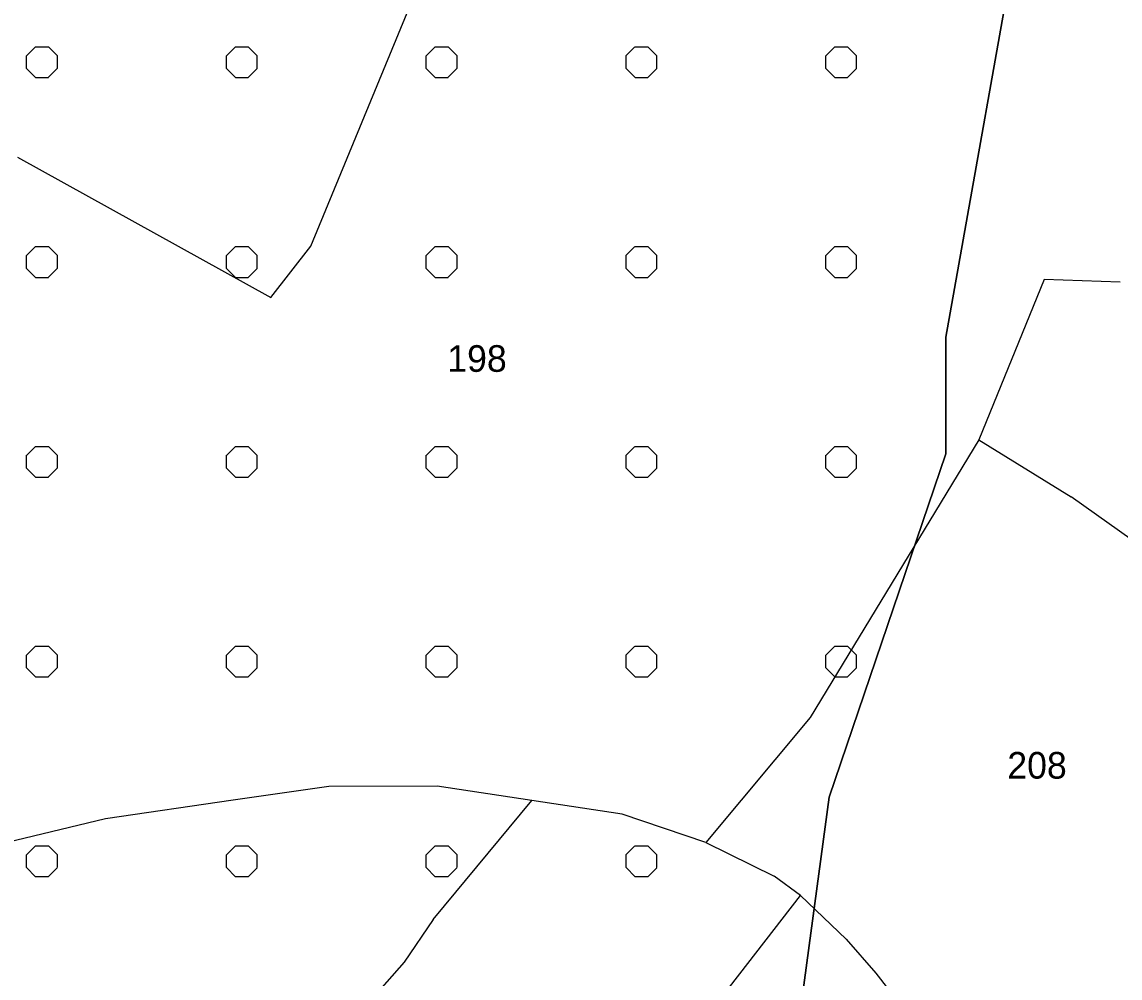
# Model space of a CAD drawing. Extents: x 410727 to 412947, y 4463506 to 4466382.
# Drawn here: x 411531.6 to 411696.5, y 4466009.6 to 4466153.2 of the extents above; entities that cross this region are included whole.
import ezdxf

# ---------------------------------------------------------------- set-up
doc = ezdxf.new("R2010")
doc.units = 0
for name, color, linetype in [('ADAKENARI', 7, 'Continuous'), ('KDS_PARSEL_NO', 7, 'Continuous'), ('KDS_PL', 7, 'Continuous'), ('PL_KA_TARIM_DIGER', 7, 'Continuous'), ('PL_KA_TARIM_OZEL', 7, 'Continuous'), ('TR_OZELMAHSUL', 7, 'Continuous')]:
    doc.layers.add(name, color=color, linetype=linetype)

msp = doc.modelspace()

# ---------------------------------------------------------------- linework, layer by layer
at = {"layer": 'ADAKENARI'}
for p, q in [((411670.3, 4466105.81), (411682.27, 4466173.05)), ((411670.3, 4466088.31), (411670.3, 4466105.81)), ((411652.8, 4466036.74), (411670.3, 4466088.31)), ((411646.35, 4465988.84), (411652.8, 4466036.74))]:
    msp.add_line(p, q, dxfattribs=at)
at = {"layer": 'KDS_PL'}
for p, q in [((411574.94, 4466119.47), (411590.62, 4466157.38)), ((411530.91, 4466132.84), (411568.94, 4466111.75)), ((411568.94, 4466111.75), (411574.94, 4466119.47)), ((411685.06, 4466114.5), (411675.28, 4466090.38)), ((411696.47, 4466114.09), (411685.06, 4466114.5)), ((411675.28, 4466090.38), (411649.91, 4466048.72)), ((411675.28, 4466090.38), (411689.12, 4466081.85)), ((411702.88, 4466072.06), (411689.12, 4466081.85)), ((411649.91, 4466048.72), (411634.28, 4466029.91)), ((411577.69, 4466038.34), (411563.31, 4466036.31)), ((411593.91, 4466038.38), (411577.69, 4466038.34)), ((411608.12, 4466036.25), (411593.91, 4466038.38)), ((411563.31, 4466036.31), (411544.12, 4466033.5)), ((411593.33, 4466018.34), (411608.12, 4466036.25)), ((411621.72, 4466034.16), (411608.12, 4466036.25)), ((411544.12, 4466033.5), (411521.38, 4466028)), ((411634.28, 4466029.91), (411621.72, 4466034.16)), ((411634.28, 4466029.91), (411644.52, 4466024.88)), ((411648.5, 4466021.99), (411644.52, 4466024.88)), ((411637.84, 4466008.22), (411648.5, 4466021.99)), ((411648.5, 4466021.99), (411655.33, 4466015.42)), ((411593.33, 4466018.34), (411588.96, 4466011.95)), ((411655.33, 4466015.42), (411659.81, 4466010.33)), ((411588.96, 4466011.95), (411584.53, 4466006.9)), ((411659.81, 4466010.33), (411664.6, 4466004.13))]:
    msp.add_line(p, q, dxfattribs=at)
at = {"layer": 'PL_KA_TARIM_DIGER'}
msp.add_lwpolyline([(411682.27, 4466173.05), (411670.3, 4466105.81), (411670.3, 4466088.31), (411652.8, 4466036.74), (411646.35, 4465988.84), (411635.3, 4465976.87), (411591.09, 4465931.74), (411538.25, 4465904.8), (411605.17, 4465869.8), (411613.8, 4465883.79), (411618.69, 4465897.02), (411620.41, 4465890.7), (411625.58, 4465882.65), (411631.77, 4465875.64), (411639.11, 4465868.28), (411648.52, 4465860.01), (411661.14, 4465849.78), (411670.66, 4465841.96), (411677.43, 4465836.56), (411684.65, 4465834.26), (411690.51, 4465834.49), (411698.65, 4465836.9)], dxfattribs=at)
at = {"layer": 'PL_KA_TARIM_OZEL'}
msp.add_lwpolyline([(411524.33, 4465912.08), (411524.97, 4465911.75), (411538.25, 4465904.8), (411538.25, 4465904.8), (411591.09, 4465931.74), (411635.3, 4465976.87), (411646.35, 4465988.84), (411652.8, 4466036.74), (411670.3, 4466088.31), (411670.3, 4466105.81), (411682.27, 4466173.05), (411679.51, 4466190.55), (411686.88, 4466263.31), (411695.17, 4466296.47), (411693.82, 4466320.72), (411344.35, 4466324.82)], dxfattribs=at)
at = {"layer": 'TR_OZELMAHSUL'}
for p, q in [((411532.28, 4466148.06), (411533.63, 4466149.41)), ((411533.64, 4466149.42), (411535.56, 4466149.42)), ((411536.91, 4466148.06), (411535.56, 4466149.41)), ((411562.28, 4466148.06), (411563.63, 4466149.41)), ((411563.64, 4466149.42), (411565.56, 4466149.42)), ((411566.91, 4466148.06), (411565.56, 4466149.41)), ((411592.27, 4466148.06), (411593.63, 4466149.41)), ((411593.64, 4466149.42), (411595.56, 4466149.42)), ((411596.91, 4466148.06), (411595.56, 4466149.41)), ((411622.27, 4466148.06), (411623.63, 4466149.41)), ((411623.64, 4466149.42), (411625.56, 4466149.42)), ((411626.91, 4466148.06), (411625.56, 4466149.41)), ((411652.27, 4466148.06), (411653.63, 4466149.41)), ((411653.64, 4466149.42), (411655.56, 4466149.42)), ((411656.91, 4466148.06), (411655.56, 4466149.41)), ((411532.29, 4466146.15), (411532.29, 4466148.07)), ((411536.91, 4466146.15), (411536.91, 4466148.07)), ((411562.29, 4466146.15), (411562.29, 4466148.07)), ((411566.91, 4466146.15), (411566.91, 4466148.07)), ((411592.29, 4466146.15), (411592.29, 4466148.07)), ((411596.91, 4466146.15), (411596.91, 4466148.07)), ((411622.29, 4466146.15), (411622.29, 4466148.07)), ((411626.91, 4466146.15), (411626.91, 4466148.07)), ((411652.29, 4466146.15), (411652.29, 4466148.07)), ((411656.91, 4466146.15), (411656.91, 4466148.07)), ((411533.64, 4466144.79), (411532.29, 4466146.14)), ((411535.55, 4466144.79), (411536.9, 4466146.14)), ((411563.64, 4466144.79), (411562.29, 4466146.14)), ((411565.55, 4466144.79), (411566.9, 4466146.14)), ((411593.64, 4466144.79), (411592.29, 4466146.14)), ((411595.54, 4466144.79), (411596.9, 4466146.14)), ((411623.64, 4466144.79), (411622.29, 4466146.14)), ((411625.54, 4466144.79), (411626.9, 4466146.14)), ((411653.64, 4466144.79), (411652.29, 4466146.14)), ((411655.54, 4466144.79), (411656.9, 4466146.14)), ((411533.64, 4466144.8), (411535.56, 4466144.8)), ((411563.64, 4466144.8), (411565.56, 4466144.8)), ((411593.64, 4466144.8), (411595.56, 4466144.8)), ((411623.64, 4466144.8), (411625.56, 4466144.8)), ((411653.64, 4466144.8), (411655.56, 4466144.8)), ((411532.28, 4466118.06), (411533.63, 4466119.41)), ((411533.64, 4466119.42), (411535.56, 4466119.42)), ((411536.91, 4466118.06), (411535.56, 4466119.42)), ((411562.28, 4466118.06), (411563.63, 4466119.41)), ((411563.64, 4466119.42), (411565.56, 4466119.42)), ((411566.91, 4466118.06), (411565.56, 4466119.42)), ((411592.27, 4466118.06), (411593.63, 4466119.41)), ((411593.64, 4466119.42), (411595.56, 4466119.42)), ((411596.91, 4466118.06), (411595.56, 4466119.42)), ((411622.27, 4466118.06), (411623.63, 4466119.41)), ((411623.64, 4466119.42), (411625.56, 4466119.42)), ((411626.91, 4466118.06), (411625.56, 4466119.42)), ((411652.27, 4466118.06), (411653.63, 4466119.41)), ((411653.64, 4466119.42), (411655.56, 4466119.42)), ((411656.91, 4466118.06), (411655.56, 4466119.42)), ((411532.29, 4466116.15), (411532.29, 4466118.07)), ((411536.91, 4466116.15), (411536.91, 4466118.07)), ((411562.29, 4466116.15), (411562.29, 4466118.07)), ((411566.91, 4466116.15), (411566.91, 4466118.07)), ((411592.29, 4466116.15), (411592.29, 4466118.07)), ((411596.91, 4466116.15), (411596.91, 4466118.07)), ((411622.29, 4466116.15), (411622.29, 4466118.07)), ((411626.91, 4466116.15), (411626.91, 4466118.07)), ((411652.29, 4466116.15), (411652.29, 4466118.07)), ((411656.91, 4466116.15), (411656.91, 4466118.07)), ((411533.64, 4466114.79), (411532.29, 4466116.15)), ((411535.55, 4466114.79), (411536.9, 4466116.14)), ((411563.64, 4466114.79), (411562.29, 4466116.15)), ((411565.55, 4466114.79), (411566.9, 4466116.14)), ((411593.64, 4466114.79), (411592.29, 4466116.15)), ((411595.54, 4466114.79), (411596.9, 4466116.14)), ((411623.64, 4466114.79), (411622.29, 4466116.15)), ((411625.54, 4466114.79), (411626.9, 4466116.14)), ((411653.64, 4466114.79), (411652.29, 4466116.15)), ((411655.54, 4466114.79), (411656.9, 4466116.14)), ((411533.64, 4466114.8), (411535.56, 4466114.8)), ((411563.64, 4466114.8), (411565.56, 4466114.8)), ((411593.64, 4466114.8), (411595.56, 4466114.8)), ((411623.64, 4466114.8), (411625.56, 4466114.8)), ((411653.64, 4466114.8), (411655.56, 4466114.8)), ((411532.28, 4466088.06), (411533.63, 4466089.41)), ((411533.64, 4466089.42), (411535.56, 4466089.42)), ((411536.91, 4466088.06), (411535.56, 4466089.42)), ((411562.28, 4466088.06), (411563.63, 4466089.41)), ((411563.64, 4466089.42), (411565.56, 4466089.42)), ((411566.91, 4466088.06), (411565.56, 4466089.42)), ((411592.27, 4466088.06), (411593.63, 4466089.41)), ((411593.64, 4466089.42), (411595.56, 4466089.42)), ((411596.91, 4466088.06), (411595.56, 4466089.42)), ((411622.27, 4466088.06), (411623.63, 4466089.41)), ((411623.64, 4466089.42), (411625.56, 4466089.42)), ((411626.91, 4466088.06), (411625.56, 4466089.42)), ((411652.27, 4466088.06), (411653.63, 4466089.41)), ((411653.64, 4466089.42), (411655.56, 4466089.42)), ((411656.91, 4466088.06), (411655.56, 4466089.42)), ((411532.29, 4466086.15), (411532.29, 4466088.07)), ((411536.91, 4466086.15), (411536.91, 4466088.07)), ((411562.29, 4466086.15), (411562.29, 4466088.07)), ((411566.91, 4466086.15), (411566.91, 4466088.07)), ((411592.29, 4466086.15), (411592.29, 4466088.07)), ((411596.91, 4466086.15), (411596.91, 4466088.07)), ((411622.29, 4466086.15), (411622.29, 4466088.07)), ((411626.91, 4466086.15), (411626.91, 4466088.07)), ((411652.29, 4466086.15), (411652.29, 4466088.07)), ((411656.91, 4466086.15), (411656.91, 4466088.07)), ((411533.64, 4466084.79), (411532.29, 4466086.15)), ((411535.55, 4466084.79), (411536.9, 4466086.14)), ((411563.64, 4466084.79), (411562.29, 4466086.15)), ((411565.55, 4466084.79), (411566.9, 4466086.14)), ((411593.64, 4466084.79), (411592.29, 4466086.15)), ((411595.54, 4466084.79), (411596.9, 4466086.14)), ((411623.64, 4466084.79), (411622.29, 4466086.15)), ((411625.54, 4466084.79), (411626.9, 4466086.14)), ((411653.64, 4466084.79), (411652.29, 4466086.15)), ((411655.54, 4466084.79), (411656.9, 4466086.14)), ((411533.64, 4466084.8), (411535.56, 4466084.8)), ((411563.64, 4466084.8), (411565.56, 4466084.8)), ((411593.64, 4466084.8), (411595.56, 4466084.8)), ((411623.64, 4466084.8), (411625.56, 4466084.8)), ((411653.64, 4466084.8), (411655.56, 4466084.8)), ((411532.28, 4466058.06), (411533.63, 4466059.41)), ((411533.64, 4466059.42), (411535.56, 4466059.42)), ((411536.91, 4466058.06), (411535.56, 4466059.42)), ((411562.28, 4466058.06), (411563.63, 4466059.41)), ((411563.64, 4466059.42), (411565.56, 4466059.42)), ((411566.91, 4466058.06), (411565.56, 4466059.42)), ((411592.27, 4466058.06), (411593.63, 4466059.41)), ((411593.64, 4466059.42), (411595.56, 4466059.42)), ((411596.91, 4466058.06), (411595.56, 4466059.42)), ((411622.27, 4466058.06), (411623.63, 4466059.41)), ((411623.64, 4466059.42), (411625.56, 4466059.42)), ((411626.91, 4466058.06), (411625.56, 4466059.42)), ((411652.27, 4466058.06), (411653.63, 4466059.41)), ((411653.64, 4466059.42), (411655.56, 4466059.42)), ((411656.91, 4466058.06), (411655.56, 4466059.42)), ((411532.29, 4466056.15), (411532.29, 4466058.07)), ((411536.91, 4466056.15), (411536.91, 4466058.07)), ((411562.29, 4466056.15), (411562.29, 4466058.07)), ((411566.91, 4466056.15), (411566.91, 4466058.07)), ((411592.29, 4466056.15), (411592.29, 4466058.07)), ((411596.91, 4466056.15), (411596.91, 4466058.07)), ((411622.29, 4466056.15), (411622.29, 4466058.07)), ((411626.91, 4466056.15), (411626.91, 4466058.07)), ((411652.29, 4466056.15), (411652.29, 4466058.07)), ((411656.91, 4466056.15), (411656.91, 4466058.07)), ((411533.64, 4466054.79), (411532.29, 4466056.15)), ((411535.55, 4466054.79), (411536.9, 4466056.14)), ((411563.64, 4466054.79), (411562.29, 4466056.15)), ((411565.55, 4466054.79), (411566.9, 4466056.14)), ((411593.64, 4466054.79), (411592.29, 4466056.15)), ((411595.54, 4466054.79), (411596.9, 4466056.14)), ((411623.64, 4466054.79), (411622.29, 4466056.15)), ((411625.54, 4466054.79), (411626.9, 4466056.14)), ((411653.64, 4466054.79), (411652.29, 4466056.15)), ((411655.54, 4466054.79), (411656.9, 4466056.14)), ((411533.64, 4466054.8), (411535.56, 4466054.8)), ((411563.64, 4466054.8), (411565.56, 4466054.8)), ((411593.64, 4466054.8), (411595.56, 4466054.8)), ((411623.64, 4466054.8), (411625.56, 4466054.8)), ((411653.64, 4466054.8), (411655.56, 4466054.8)), ((411532.28, 4466028.06), (411533.63, 4466029.41)), ((411532.29, 4466026.15), (411532.29, 4466028.07)), ((411533.64, 4466029.42), (411535.56, 4466029.42)), ((411536.91, 4466028.06), (411535.56, 4466029.42)), ((411536.91, 4466026.15), (411536.91, 4466028.07)), ((411562.28, 4466028.06), (411563.63, 4466029.41)), ((411562.29, 4466026.15), (411562.29, 4466028.07)), ((411563.64, 4466029.42), (411565.56, 4466029.42)), ((411566.91, 4466028.06), (411565.56, 4466029.42)), ((411566.91, 4466026.15), (411566.91, 4466028.07)), ((411592.27, 4466028.06), (411593.63, 4466029.41)), ((411592.29, 4466026.15), (411592.29, 4466028.07)), ((411593.64, 4466029.42), (411595.56, 4466029.42)), ((411596.91, 4466028.06), (411595.56, 4466029.42)), ((411596.91, 4466026.15), (411596.91, 4466028.07)), ((411622.27, 4466028.06), (411623.63, 4466029.41)), ((411622.29, 4466026.15), (411622.29, 4466028.07)), ((411623.64, 4466029.42), (411625.56, 4466029.42)), ((411626.91, 4466028.06), (411625.56, 4466029.42)), ((411626.91, 4466026.15), (411626.91, 4466028.07)), ((411533.64, 4466024.79), (411532.29, 4466026.15)), ((411533.64, 4466024.8), (411535.56, 4466024.8)), ((411535.55, 4466024.79), (411536.9, 4466026.14)), ((411563.64, 4466024.79), (411562.29, 4466026.15)), ((411563.64, 4466024.8), (411565.56, 4466024.8)), ((411565.55, 4466024.79), (411566.9, 4466026.14)), ((411593.64, 4466024.79), (411592.29, 4466026.15)), ((411593.64, 4466024.8), (411595.56, 4466024.8)), ((411595.54, 4466024.79), (411596.9, 4466026.14)), ((411623.64, 4466024.79), (411622.29, 4466026.15)), ((411623.64, 4466024.8), (411625.56, 4466024.8)), ((411625.54, 4466024.79), (411626.9, 4466026.14))]:
    msp.add_line(p, q, dxfattribs=at)

# ---------------------------------------------------------------- texts
at = {"layer": 'KDS_PARSEL_NO'}
for s, p in [('198', (411595.45, 4466100.61)), ('208', (411679.53, 4466039.52))]:
    msp.add_text(s, height=4, dxfattribs=at).set_placement(p)

doc.saveas('drawing.dxf')
